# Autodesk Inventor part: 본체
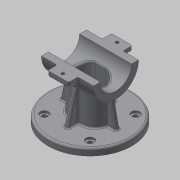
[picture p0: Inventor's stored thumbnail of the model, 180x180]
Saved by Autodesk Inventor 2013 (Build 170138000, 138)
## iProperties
Created: 2015-12
Part Number: 본체
Material: 알루미늄 6061
Document SubType Name: Modeling
Designer: mduedu
Density: 2.71 g/cm^3
Author: mduedu
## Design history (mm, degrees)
sketch "스케치1"
  geometry: L1 (45, 40)-(-45, 40); L2 (-45, 40)-(-45, -40); L3 (-45, -40)-(45, -40); L4 (45, -40)-(45, 40); L5 (45, 40)-(-45, -40); L6 (-45, 40)-(45, -40); 2 further points
  constraints: 12 end point, 2 midpoint, 2 parallel, 1 coincident, 1 horizontal, 1 perpendicular, 3 other
  dimensions: "d0" = 90 distance of L2.end L3.end; "d2" = 80 distance of L1.end L2.end
extrude "돌출1" new body sketch "스케치1" distance "d3" = 10; taper "d4" = 0 deg
sketch "스케치2"
  geometry: C1 r 32.5 at (80, 0); 1 further point
  constraints: 1 centre point
  dimensions: "d5" = 65 diameter of C1; "d116" = 80 distance of point (0, 0) C1.centre
extrude "돌출2" join sketch "스케치2" stored distance "d7" = 75; taper "d8" = 0 deg
sketch "스케치3"
  geometry: L1 (-27.5, -20)-(27.5, -20); L2 (27.5, -20)-(27.5, 20); L3 (27.5, 20)-(-27.5, 20); L4 (-27.5, 20)-(-27.5, -20); L5 (-27.5, -20)-(27.5, 20); L6 (27.5, -20)-(-27.5, 20); 1 further point
  constraints: 12 end point, 2 midpoint, 2 parallel, 1 horizontal, 1 perpendicular
  dimensions: "d9" = 55 distance of L2.end L3.end; "d11" = 40 distance of L1.end L2.end
extrude "돌출3" new body sketch "스케치3" stored distance "d12" = 75; taper "d13" = 0 deg
fillet "모깎기1"
fillet "모깎기2"
feature "결합1"
  node "솔리드2"
sketch "스케치4"
  geometry: L1 (-37.5, 47.5)-(37.5, 47.5) reference; L2 (32.5, 47.5)-(40.208, 10); L3 (37.5, 47.5)-(37.5, 112.5) reference; L4 (60.208, 0)-(60.208, 10) reference; L5 (60.208, 10)-(-60.208, 10) reference; 1 further point
  constraints: 2 end point, 2 point on line
  dimensions: "d15" = 5 distance from line of L2.start L3; "d117" = 20 distance from line of L2.end L4
sketch "스케치5"
  geometry: L1 (10, 35.208)-(56.729, 22.687); L2 (0, 60.208)-(10, 60.208) reference; L3 (10, -60.208)-(10, 60.208) reference; 2 further points
  constraints: 2 end point, 1 point on line, 2 other
  dimensions: "d118" = 25 distance from line of L1.start L2; "d119" = 75 deg angle of L1 L3
feature "리브1" dims "d19" = 1, "d20" = 6, "d21" = 0, "d22" = 0, "d23" = 1, "d24" = 1
feature "리브2" dims "d25" = 1, "d26" = 6, "d27" = 0, "d28" = 0, "d29" = 1, "d30" = 1
fillet "모깎기4" dims "d31" = 2
fillet "모깎기5" dims "d32" = 2
fillet "모깎기6" dims "d33" = 2
sketch "스케치6"
  geometry: L1 (0, 0)-(-32.88, 32.88); L2 (0, 0)-(-46.5, 0); A1 r 46.5 centre (0, 0) between (-32.88, 32.88) and (-46.5, 0); 5 further points
  constraints: 4 end point, 2 coincident, 2 point on circle, 1 centre point, 1 horizontal, 5 other
  dimensions: "d120" = 93 diameter of A1; "d122" = 45 deg angle of L1 L2; "d126" = 360 deg dimension on point (0, 0) point (-32.88, 32.88) (derived)
hole "구멍1" sketch "스케치6" at (-32.88, 32.88), (-32.88, -32.88), (32.88, -32.88), (32.88, 32.88) diameter "d34" = 7; stored, may be unused: countersink angle "d38" = 90 deg, drill point angle "d40" = 118 deg; dims "d35" = 6, "d36" = 12, "d37" = 3, "d39" = 8
fillet "모깎기13" dims "d131" = 3
hole "구멍2" diameter "d44" = 45; stored, may be unused: countersink angle "d48" = 90 deg, drill point angle "d50" = 118 deg; dims "d42" = 10, "d43" = 10, "d45" = 6, "d46" = 4, "d47" = 2, "d49" = 8
sketch "스케치7" dims "d52" = 26.5
  geometry: L1 (0, 0)-(32.5, 0); L2 (0, 0)-(22.981, 22.981); A1 r 32.5 centre (0, 0) between (32.5, 0) and (22.981, 22.981) reference; 3 further points
  constraints: 4 end point, 2 point on circle, 1 coincident, 1 horizontal, 1 point on line, 3 other
  dimensions: "d51" = 45 deg angle of L2 L1
hole "구멍3" sketch "스케치7" at (18.738, 18.738) diameter "d54" = 2.459; stored, may be unused: countersink angle "d58" = 90 deg, drill point angle "d60" = 118 deg; dims "d55" = 8, "d56" = 4, "d57" = 2, "d59" = 10
sketch "스케치8"
  geometry: L1 (72.5, 31.623)-(72.5, 46); L2 (72.5, 46)-(87.5, 46); L3 (87.5, 46)-(87.5, 31.623); A1 r 32.5 centre (80, 0) between (87.5, 31.623) and (72.5, 31.623) reference; 2 further points
  constraints: 6 end point, 2 point on circle, 1 horizontal, 1 midpoint, 1 parallel, 1 vertical, 1 vertical alignment
  dimensions: "d64" = 15 distance of L1.end L2.end; "d66" = 46 distance from line of L2 A1.centre
extrude "돌출4" join sketch "스케치8" stored distance "d67" = 30; taper "d68" = 0 deg
fillet "모깎기8" dims "d69" = 3
fillet "모깎기9" dims "d70" = 2
node "작업 평면2"
sketch "스케치16"
  geometry: L1 (33.166, 72.5)-(44, 72.5) reference; L2 (42.5, 72.5)-(28.53, 64.434); L3 (46, 75.5)-(46, 84.5) reference; 2 further points
  constraints: 2 end point, 1 point on line, 2 other
  dimensions: "d138" = 30 deg angle of L2 L1; "d139" = 3.5 distance from line of L2.start L3
feature "리브3" sketch "스케치16" dims "d140" = 1, "d141" = 3, "d142" = 0, "d143" = 0, "d144" = 1, "d145" = 1
fillet "모깎기14" dims "d146" = 1
fillet "모깎기15" dims "d147" = 1
sketch "스케치9"
  geometry: L1 (-76, 82.5)-(76, 82.5); L2 (76, 82.5)-(76, 0); L3 (76, 0)-(-76, 0); L4 (-76, 0)-(-76, 82.5); L5 (-46, 4.5)-(-46, -4.5) reference; C1 r 32.5 at (0, 0) reference; 2 further points
  constraints: 8 end point, 2 parallel, 1 coincident, 1 horizontal, 1 midpoint, 1 perpendicular
  dimensions: "d71" = 50 distance edge to line of C1 L1; "d72" = 30 distance between parallel lines of L4 L5
extrude "돌출5" cut sketch "스케치9" stored distance "d73" = 0; taper "d74" = 0 deg
node "작업 평면1"
sketch "스케치10"
  geometry: L1 (-7.5, 15)-(7.5, 15); L2 (-7.5, -15)-(7.5, -15); A1 r 20 centre (-7.5, 0) between (-7.5, 20) and (-26.977, 4.545) reference; A2 r 20 centre (7.5, 0) between (26.977, 4.545) and (7.5, 20) reference; A3 r 15 centre (-7.5, 0) between (-7.5, 15) and (-7.5, -15); A4 r 15 centre (7.5, 0) between (7.5, -15) and (7.5, 15); 1 further point
  constraints: 7 point on circle, 4 end point, 4 tangent, 3 point on line, 2 centre point, 2 coincident, 1 horizontal
  dimensions: "d77" = 5 radial gap between concentric circles of A3 A1
extrude "돌출6" cut sketch "스케치10" stored distance "d78" = 50; taper "d79" = 0 deg
fillet "모깎기10" dims "d80" = 3
sketch "스케치11"
  geometry: 2 further points
  constraints: 1 coincident
hole "구멍4" sketch "스케치11" at (0, 0) diameter "d81" = 12; stored, may be unused: countersink angle "d85" = 90 deg, drill point angle "d87" = 118 deg; dims "d82" = 8, "d83" = 40, "d84" = 10, "d86" = 10
sketch "스케치12"
  geometry: C1 r 10 at (0, 0); 1 further point
  constraints: 1 centre point, 1 coincident
  dimensions: "d88" = 20 diameter of C1
extrude "돌출7" cut sketch "스케치12" distance "d89" = 5; taper "d90" = 0 deg
chamfer "모따기1" distance "d91" = 1; stored, may be unused: second distance "d92" = 2, angle "d93" = 45 deg
fillet "모깎기11" dims "d94" = 0.5
sketch "스케치13"
  geometry: L1 (-3, 10.834)-(-3, 1.039) reference; L2 (27, 1.039)-(27, 10.834) reference; L3 (-3, 5.936)-(27, 5.936); L4 (24, 12.834)-(0, 12.834) reference; L5 (12, 12.834)-(12, -33.166); 1 further point
  constraints: 4 end point, 4 midpoint, 1 perpendicular, 1 point on line
hole "구멍5" sketch "스케치13" at (12, 5.936) diameter "d101" = 4.5; stored, may be unused: countersink angle "d105" = 90 deg, drill point angle "d107" = 0 deg; dims "d102" = 6, "d103" = 4, "d104" = 2, "d106" = 8
fillet "모깎기12" dims "d115" = 0.3
node "솔리드1"
mirror "대칭1"
mirror "대칭2"
pattern_circular "원형 패턴1" dims angle "d62" = 360 deg
mirror "대칭3"
mirror "대칭7"
mirror "대칭4"
mirror "대칭6"
other parameters: "d137" = -5
